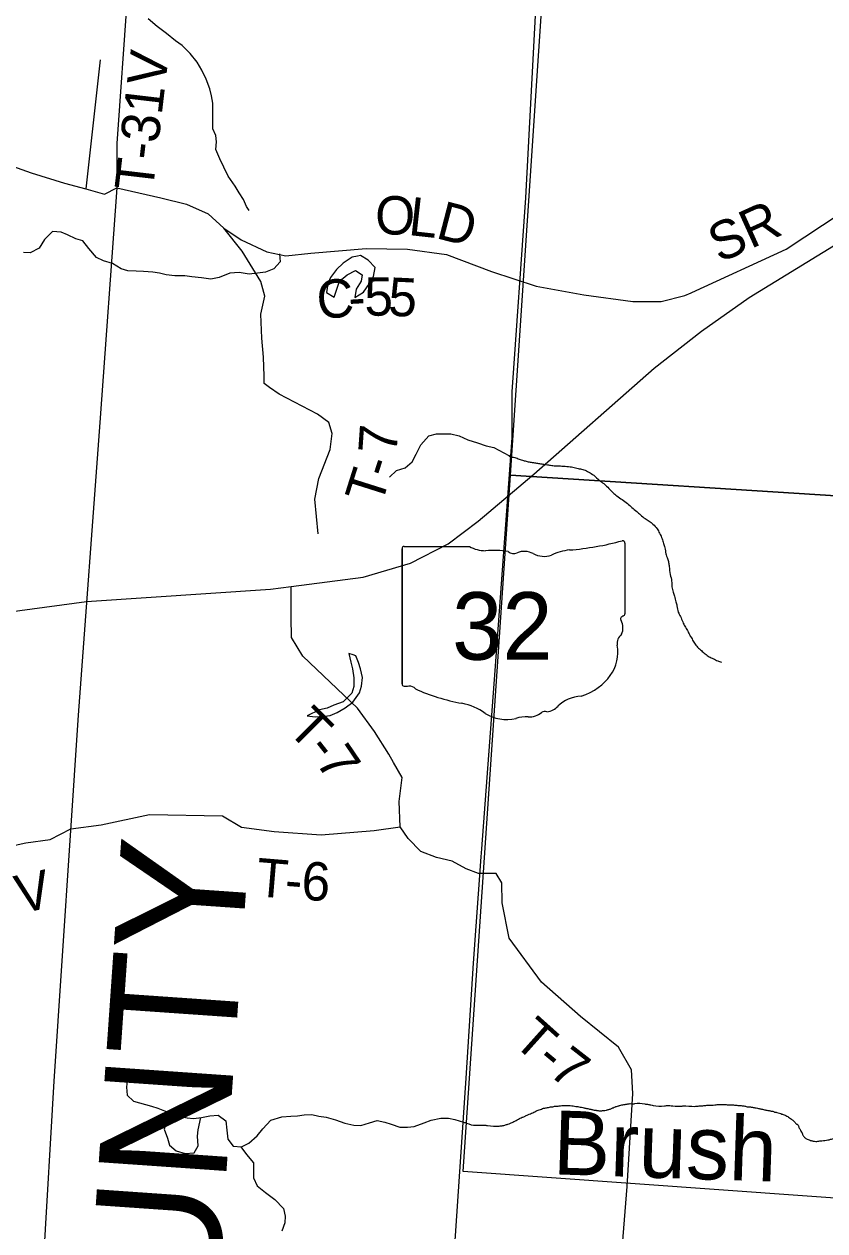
# Model space of a CAD drawing. Extents: x -15 to 405, y -40 to 87.
# Drawn here: x 3.536 to 4.721, y 17.808 to 19.593 of the extents above; entities that cross this region are included whole.
import ezdxf

# ---------------------------------------------------------------- set-up
doc = ezdxf.new("R2010")
doc.units = 0
for name, color, linetype in [('GM_P_State_Alignment', 7, 'Continuous'), ('GM_P_State_Location', 7, 'Continuous'), ('GM_X_Adjacent_County_Text', 7, 'Continuous'), ('GM_X_Airport_Location_Class_2', 7, 'Continuous'), ('GM_X_Minor_Lake', 7, 'Continuous'), ('GM_X_Minor_Lake_Text', 7, 'Continuous'), ('GM_X_Minor_River', 7, 'Continuous'), ('GM_X_Section_Text', 7, 'Continuous'), ('GM_X_State_Location', 7, 'Continuous'), ('GM_X_State_Route', 7, 'Continuous'), ('GM_X_Township_Subdivision', 7, 'Continuous'), ('GM_X_Township_Text', 7, 'Continuous')]:
    doc.layers.add(name, color=color, linetype=linetype)

msp = doc.modelspace()

# ---------------------------------------------------------------- linework, layer by layer
at = {"layer": 'GM_P_State_Location'}
for points in [[(3.6488, 19.5407), (3.6273, 19.3495)], [(3.9712, 18.839), (3.9663, 18.8906), (3.9723, 18.921), (3.989, 18.9639), (3.9916, 18.9878), (3.9871, 19.0038), (3.97, 19.0163), (3.9134, 19.0459), (3.8993, 19.0555), (3.8911, 19.0615), (3.8913, 19.0725), (3.8902, 19.1006), (3.8879, 19.1287), (3.8863, 19.1644), (3.892, 19.1906), (3.8863, 19.2126), (3.8586, 19.2574), (3.8316, 19.2916)], [(4.0826, 18.5005), (4.0824, 18.5008), (4.0755, 18.5128), (4.0546, 18.5466), (4.0291, 18.5811), (3.9482, 18.6582), (3.9318, 18.6859), (3.9314, 18.7159), (3.9312, 18.7613)], [(4.4151, 17.7062), (4.4283, 17.8734), (4.4366, 18.0109), (4.4347, 18.0458), (4.4156, 18.0792), (4.359, 18.1248), (4.3017, 18.1756), (4.2538, 18.2409), (4.2435, 18.293), (4.2427, 18.3226), (4.2343, 18.3363), (4.2188, 18.3363), (4.2081, 18.3362), (4.1899, 18.3435), (4.1694, 18.3545), (4.1462, 18.3601), (4.123, 18.3689), (4.104, 18.3882), (4.0926, 18.4053), (4.0911, 18.4429), (4.0953, 18.4786), (4.0826, 18.5005)], [(3.2241, 18.2382), (3.247, 18.2857), (3.2998, 18.3863), (3.3118, 18.4075), (3.3179, 18.4159), (3.3273, 18.4167), (3.3687, 18.4077), (3.3941, 18.4001), (3.4374, 18.3805), (3.4658, 18.3688), (3.4829, 18.367), (3.5071, 18.375), (3.5389, 18.3819), (3.5749, 18.3869), (3.605, 18.4026)], [(3.605, 18.4026), (3.6499, 18.4085), (3.7216, 18.4237), (3.8298, 18.4219), (3.8576, 18.4048), (3.9062, 18.3987), (3.9753, 18.3935), (4.0539, 18.4), (4.0926, 18.4053)]]:
    msp.add_lwpolyline(points, dxfattribs=at)
at = {"layer": 'GM_X_Adjacent_County_Text'}
for points in [[(3.8692, 19.3175), (3.8652, 19.3236), (3.8607, 19.3338), (3.8542, 19.3436), (3.8485, 19.3535), (3.8379, 19.3683), (3.8315, 19.3815), (3.8258, 19.394), (3.8197, 19.4077), (3.8208, 19.419), (3.8197, 19.4285), (3.8151, 19.4384), (3.8151, 19.4486), (3.8155, 19.4623), (3.8151, 19.4763), (3.8135, 19.4873), (3.8109, 19.4975), (3.8052, 19.5119), (3.7991, 19.5255), (3.7923, 19.5373), (3.782, 19.5498), (3.7699, 19.5619), (3.76, 19.5687), (3.7468, 19.5793), (3.7331, 19.5899), (3.7195, 19.6013)], [(3.9139, 19.2536), (3.915, 19.2417), (3.9055, 19.2311), (3.893, 19.2265), (3.8816, 19.2246), (3.8688, 19.2235), (3.8544, 19.2257), (3.8404, 19.225), (3.8248, 19.2185), (3.8123, 19.2158), (3.7987, 19.2181), (3.7843, 19.2192), (3.7737, 19.2207), (3.7593, 19.2207), (3.7464, 19.2222), (3.7366, 19.2248), (3.7267, 19.2263), (3.7127, 19.2274), (3.7021, 19.2278), (3.6896, 19.2282), (3.6797, 19.2312), (3.6669, 19.2391), (3.6536, 19.2433), (3.643, 19.2482), (3.632, 19.2614), (3.6229, 19.2728), (3.6126, 19.2758), (3.6005, 19.2815), (3.5907, 19.2857), (3.5782, 19.2864), (3.5664, 19.2746), (3.5585, 19.2617), (3.5452, 19.2549), (3.5354, 19.2556)], [(4.0768, 18.9228), (4.0869, 18.933), (4.0998, 18.9368), (4.11, 18.9455), (4.1161, 18.9569), (4.1232, 18.971), (4.135, 18.9839), (4.1463, 18.9873), (4.1672, 18.9873), (4.1797, 18.9843), (4.1925, 18.9783), (4.2066, 18.9737), (4.2195, 18.9692), (4.2312, 18.9669), (4.2533, 18.9549)], [(3.6885, 18.0298), (3.6876, 18.0201), (3.6884, 18.0084), (3.6979, 17.9997), (3.7244, 17.9921), (3.7339, 17.9891), (3.7437, 17.9853), (3.7566, 17.9804), (3.7661, 17.9774), (3.7771, 17.9748), (3.7866, 17.974), (3.7983, 17.9755), (3.8108, 17.9778), (3.8233, 17.9786), (3.8347, 17.9703), (3.8362, 17.9566), (3.8374, 17.943), (3.8453, 17.9331), (3.8578, 17.932), (3.8684, 17.9373), (3.8809, 17.948), (3.8892, 17.9586), (3.901, 17.9715), (3.9172, 17.9761), (3.9305, 17.9772), (3.9403, 17.9776), (3.9506, 17.9792), (3.9619, 17.9799), (3.9722, 17.9773), (3.9828, 17.9758), (3.9968, 17.9716), (4.0104, 17.9671), (4.0237, 17.9637), (4.0343, 17.9634), (4.0468, 17.9675), (4.0585, 17.971), (4.0695, 17.9683), (4.079, 17.9653), (4.0919, 17.9612), (4.1032, 17.9608), (4.1131, 17.962), (4.1279, 17.9673), (4.1385, 17.9711), (4.1525, 17.9741), (4.1638, 17.9742), (4.1733, 17.9723), (4.1862, 17.9685)], [(3.7517, 17.9823), (3.7472, 17.9705), (3.7434, 17.958), (3.748, 17.9448), (3.751, 17.9345), (3.7612, 17.9258), (3.7745, 17.922), (3.7878, 17.9228), (3.7934, 17.9334), (3.7927, 17.9475), (3.7938, 17.957), (3.7977, 17.9755)], [(3.8565, 17.9321), (3.865, 17.9203), (3.8753, 17.9082), (3.8753, 17.8862), (3.881, 17.874), (3.8931, 17.8642), (3.9068, 17.854), (3.9197, 17.8407), (3.9223, 17.8293), (3.9216, 17.8195), (3.9175, 17.807)]]:
    msp.add_lwpolyline(points, dxfattribs=at)
for points in [[(4.2533, 18.9557), (4.2533, 18.9549), (4.26, 18.9524), (4.2668, 18.9503), (4.2732, 18.9482), (4.2788, 18.9465), (4.2845, 18.9452), (4.2913, 18.9442), (4.2969, 18.9432), (4.3034, 18.9423), (4.3102, 18.9413), (4.3166, 18.9403), (4.3238, 18.9397), (4.3314, 18.9394), (4.3416, 18.9387), (4.3499, 18.9373), (4.3574, 18.9355), (4.3642, 18.9338), (4.3713, 18.9305), (4.3787, 18.9257), (4.3872, 18.9182), (4.3935, 18.9134), (4.4012, 18.906), (4.4071, 18.9001), (4.413, 18.8953), (4.4208, 18.8897), (4.4286, 18.8838), (4.4352, 18.8782), (4.4423, 18.8723), (4.4478, 18.8672), (4.4548, 18.8616), (4.4608, 18.858), (4.4663, 18.8533), (4.4725, 18.8466), (4.4761, 18.84), (4.48, 18.8316), (4.4817, 18.825), (4.4841, 18.8185), (4.4854, 18.8097), (4.4878, 18.8024), (4.4895, 18.7967), (4.4904, 18.7906), (4.4919, 18.7791), (4.4939, 18.7692), (4.4943, 18.7604), (4.4964, 18.7528), (4.4981, 18.747), (4.5001, 18.7382), (4.5018, 18.7324), (4.5037, 18.7233), (4.5069, 18.7167), (4.5105, 18.7086), (4.5133, 18.7024), (4.5173, 18.6958), (4.5208, 18.6893), (4.5241, 18.6835), (4.5277, 18.6773), (4.5324, 18.6714), (4.5379, 18.6663), (4.5435, 18.6615), (4.5494, 18.6572), (4.5557, 18.6543), (4.5621, 18.651), (4.5677, 18.649)], [(4.1862, 17.9685), (4.1905, 17.967), (4.2041, 17.9638), (4.2068, 17.9641), (4.2129, 17.9639), (4.2189, 17.9637), (4.2216, 17.9633), (4.239, 17.9627), (4.2421, 17.963), (4.2444, 17.9633), (4.247, 17.9639), (4.2497, 17.965), (4.2516, 17.9653), (4.2555, 17.9667), (4.2605, 17.9692), (4.2674, 17.9728), (4.2728, 17.9756), (4.2751, 17.9763), (4.279, 17.9781), (4.2833, 17.9802), (4.2902, 17.983), (4.2964, 17.9862), (4.2998, 17.9873), (4.3063, 17.9893), (4.309, 17.9896), (4.3147, 17.9909), (4.3182, 17.9912), (4.3208, 17.9919), (4.3277, 17.9924), (4.3315, 17.993), (4.3342, 17.993), (4.3391, 17.9932), (4.3418, 17.9931), (4.3463, 17.9926), (4.3482, 17.9925), (4.3523, 17.9916), (4.355, 17.9915), (4.3588, 17.9906), (4.3607, 17.9906), (4.364, 17.9897), (4.3655, 17.9893), (4.3682, 17.9888), (4.3716, 17.9879), (4.3731, 17.9875), (4.3746, 17.9874), (4.3765, 17.987), (4.378, 17.9866), (4.3806, 17.9861), (4.3821, 17.9861), (4.3836, 17.9856), (4.3855, 17.9856), (4.3874, 17.9851), (4.3897, 17.985), (4.3916, 17.9854), (4.3935, 17.9857), (4.3969, 17.9859), (4.3985, 17.9867), (4.4, 17.987), (4.4019, 17.9877), (4.4038, 17.988), (4.4058, 17.9891), (4.4073, 17.9898), (4.4108, 17.9912), (4.4123, 17.9915), (4.4154, 17.9925), (4.4169, 17.9929), (4.4204, 17.9939), (4.4219, 17.9942), (4.4246, 17.9945), (4.4261, 17.9949), (4.4284, 17.9952), (4.4299, 17.9955), (4.4326, 17.9958), (4.4375, 17.9956), (4.4394, 17.9959), (4.4542, 17.9954), (4.4565, 17.995), (4.4584, 17.9949), (4.4606, 17.9945), (4.4633, 17.994), (4.4666, 17.9931), (4.4833, 17.9926), (4.4864, 17.9929), (4.4959, 17.9925), (4.5084, 17.9921), (4.5107, 17.9924), (4.5285, 17.9918), (4.5315, 17.9921), (4.5349, 17.9924), (4.5388, 17.9926), (4.5445, 17.9932), (4.5471, 17.9935), (4.5532, 17.9937), (4.5578, 17.9939)], [(4.5578, 17.9939), (4.5597, 17.9942), (4.5654, 17.9944), (4.5673, 17.9944), (4.5734, 17.9945), (4.576, 17.9941), (4.5855, 17.9938), (4.5919, 17.9932), (4.5938, 17.9931), (4.5999, 17.9925), (4.6021, 17.9921), (4.6044, 17.9916), (4.607, 17.9911), (4.6093, 17.9911), (4.6116, 17.9906), (4.6138, 17.9905), (4.6153, 17.9901), (4.6172, 17.9897), (4.6191, 17.9896), (4.6225, 17.9887), (4.6244, 17.9883), (4.627, 17.9878), (4.63, 17.987), (4.6346, 17.986), (4.638, 17.9856), (4.6402, 17.9851), (4.6421, 17.9847), (4.6448, 17.9842), (4.6463, 17.9834), (4.6478, 17.9833), (4.6496, 17.9825), (4.6534, 17.9816), (4.6572, 17.9804), (4.659, 17.9799), (4.6617, 17.9787), (4.6669, 17.9759), (4.6724, 17.9719), (4.6758, 17.9687), (4.6787, 17.9656), (4.6802, 17.9648), (4.6816, 17.9625), (4.6823, 17.9605), (4.6845, 17.9567), (4.6852, 17.9551), (4.687, 17.9524), (4.6873, 17.9509), (4.688, 17.9493), (4.6891, 17.9478), (4.6924, 17.9442), (4.6946, 17.943), (4.6973, 17.9422), (4.6991, 17.9414), (4.7014, 17.9409), (4.7033, 17.9405), (4.7074, 17.9399), (4.7101, 17.9402), (4.7162, 17.9408), (4.725, 17.942), (4.7292, 17.943), (4.7349, 17.9447), (4.7368, 17.945), (4.7387, 17.9435), (4.7401, 17.9411), (4.7415, 17.9381), (4.743, 17.9353), (4.7441, 17.9334), (4.7451, 17.9319), (4.7469, 17.928), (4.748, 17.9264), (4.7505, 17.9226), (4.7509, 17.921), (4.753, 17.9172), (4.7548, 17.9144), (4.7559, 17.9129), (4.757, 17.9109), (4.758, 17.9086), (4.7598, 17.9052), (4.762, 17.9009), (4.7641, 17.8978), (4.7659, 17.8939), (4.7669, 17.8912), (4.7691, 17.8881), (4.7706, 17.8854), (4.7723, 17.8819), (4.7734, 17.8792), (4.7748, 17.8765), (4.7766, 17.8727), (4.7776, 17.87), (4.7791, 17.8673), (4.7812, 17.8619), (4.7833, 17.858), (4.7843, 17.8542), (4.7865, 17.8515), (4.7887, 17.848), (4.7904, 17.8437), (4.7926, 17.841), (4.7937, 17.8391)]]:
    msp.add_spline(points, degree=3, dxfattribs=at)
at = {"layer": 'GM_X_Airport_Location_Class_2'}
for points in [[(5.3465, 19.8721), (5.28, 18.8608), (4.2557, 18.9261), (4.3229, 19.9309)], [(4.2557, 18.9261), (5.28, 18.8608), (5.2536, 18.4962), (5.2191, 18.0246), (5.2034, 17.8226), (4.1856, 17.8953)]]:
    msp.add_lwpolyline(points, close=True, dxfattribs=at)
msp.add_lwpolyline([(4.047, 15.9545), (4.0777, 16.4138), (4.1093, 16.7849), (4.1132, 16.8456), (4.1173, 16.8769), (4.1204, 16.9125), (4.1207, 16.9338), (4.126, 17.0077), (4.1648, 17.662), (4.1898, 18.0333), (4.2008, 18.2037), (4.2124, 18.3609), (4.2133, 18.373), (4.2327, 18.6367), (4.2582, 18.9809), (4.2581, 19.0493), (4.2782, 19.3362), (4.2938, 19.625)], dxfattribs=at)
at = {"layer": 'GM_X_Section_Text'}
for points in [[(4.0291, 19.25), (4.0214, 19.2483), (4.0081, 19.2396), (3.9983, 19.2305), (3.9892, 19.2183), (3.9855, 19.2089), (3.9832, 19.1963), (3.9946, 19.1895)], [(3.9946, 19.1895), (3.9991, 19.2024), (4.0029, 19.2131), (4.0142, 19.2222), (4.0263, 19.2286), (4.0362, 19.2226), (4.0347, 19.2131), (4.0275, 19.2013), (4.0253, 19.1888), (4.0381, 19.1968), (4.0468, 19.2097), (4.0529, 19.2199), (4.0555, 19.2332), (4.0453, 19.2442), (4.0335, 19.251), (4.0291, 19.25)], [(4.0227, 18.6598), (4.0164, 18.6618), (4.0195, 18.6493), (4.0217, 18.6394), (4.024, 18.6258), (4.024, 18.6129), (4.021, 18.6034), (4.0082, 18.5905), (3.9945, 18.5855), (3.9843, 18.581), (3.973, 18.5787), (3.9548, 18.5696)], [(3.9548, 18.5696), (3.9669, 18.5681), (3.9775, 18.5688), (3.9889, 18.5704), (3.9991, 18.5746), (4.0112, 18.5818), (4.0226, 18.5901), (4.032, 18.6038), (4.0354, 18.6137), (4.0369, 18.6266), (4.0335, 18.6391), (4.0308, 18.6489), (4.027, 18.6584), (4.0227, 18.6598)]]:
    msp.add_lwpolyline(points, dxfattribs=at)
at = {"layer": 'GM_X_State_Location'}
for points in [[(3.6285, 18.7389), (3.9004, 18.7574), (3.9312, 18.7613), (4.0377, 18.7747), (4.1078, 18.7957), (4.1635, 18.8242), (4.2079, 18.8577), (4.2901, 18.9273), (4.4681, 19.0844), (4.5379, 19.1388), (4.6087, 19.1886), (4.8734, 19.3513)], [(2.1045, 18.5677), (2.1196, 18.5764), (2.2112, 18.6006), (2.2798, 18.6044), (2.4597, 18.6209), (2.7276, 18.6453), (2.8994, 18.661), (3.3688, 18.7037), (3.6285, 18.7389)]]:
    msp.add_lwpolyline(points, dxfattribs=at)
at = {"layer": 'GM_X_State_Route'}
for p, q in [((3.6935, 19.7035), (3.6734, 19.4166)), ((3.6734, 19.4166), (3.6733, 19.351)), ((3.6733, 19.351), (3.648, 19.004)), ((3.648, 19.004), (3.6161, 18.5709)), ((3.6161, 18.5709), (3.5801, 18.0292)), ((3.5801, 18.0292), (3.5413, 17.375))]:
    msp.add_line(p, q, dxfattribs=at)
at = {"layer": 'GM_X_Township_Subdivision'}
for p, q in [((4.4249, 18.8254), (4.4249, 18.7208)), ((4.0953, 18.817), (4.0953, 18.6169)), ((4.0953, 18.6169), (4.0953, 18.817)), ((4.0953, 18.6169), (4.0953, 18.817)), ((4.0985, 18.8205), (4.1951, 18.8205)), ((4.4248, 18.7208), (4.4249, 18.7208))]:
    msp.add_line(p, q, dxfattribs=at)
for centre, major_axis, start_param, end_param in [((4.3075, 19.0933), (0.3495, 0), 4.814394, 5.042369), ((4.4212, 18.8259), (0.00367, 0), 6.141152, 7.989035), ((4.0991, 18.8175), (0.00382, 0), 1.712693, 3.28349), ((4.218, 18.8437), (0.037, 0), 4.042523, 4.731795), ((4.2303, 18.7081), (0.133, 0), 1.404758, 1.657858), ((4.2605, 18.8185), (0.0107, 0), 3.836095, 5.185415), ((4.2762, 18.7954), (0.0222, 0), 0.950623, 2.079405), ((4.3049, 18.8271), (0.0267, 0), 4.081561, 5.145723), ((4.3521, 18.7594), (0.0703, 0), 1.699011, 2.107814), ((4.424, 18.7131), (0.00568, 0), 1.883978, 3.671073), ((4.421, 18.7204), (0.00393, 0), 5.05454, 6.418171), ((4.3879, 18.6998), (0.0341, 0), 5.934695, 6.695948), ((4.438, 18.6769), (0.0248, 0), 2.387724, 3.262537), ((4.3271, 18.6636), (0.0874, 0), 5.101752, 6.440018), ((4.0991, 18.6165), (0.00385, 0), 3.00124, 4.508301), ((4.0997, 18.637), (0.0294, 0), 4.665946, 4.897461), ((4.1057, 18.6054), (0.0106, 0), 0.519207, 1.627899), ((4.2395, 18.7852), (0.2524, 0), 4.195997, 4.488961), ((4.3639, 18.5607), (0.0479, 0), 1.647645, 2.488434), ((4.1643, 18.527), (0.079, 0), 0.823519, 1.323587), ((4.2497, 18.6044), (0.0501, 0), 4.026481, 4.996735), ((4.2823, 18.5894), (0.0267, 0), 4.691044, 5.507374), ((4.3065, 18.57), (0.00752, 0), 1.147584, 2.315152), ((4.3033, 18.5975), (0.0282, 0), 4.937069, 5.64225), ((4.2786, 18.5352), (0.0412, 0), 1.495662, 1.94098)]:
    msp.add_ellipse(centre, major_axis=major_axis, ratio=0.8, start_param=start_param, end_param=end_param, dxfattribs=at)
at = {"layer": 'GM_X_Township_Text'}
for points in [[(4.5228, 19.1959), (4.5237, 19.1963), (4.6636, 19.2602), (4.852, 19.3852), (4.9689, 19.4659)], [(3.3301, 19.3921), (3.3445, 19.405), (3.3638, 19.4172), (3.3702, 19.4194), (3.3764, 19.4206), (3.3918, 19.4213), (3.402, 19.4204), (3.4118, 19.4182), (3.4275, 19.4139), (3.465, 19.4038), (3.4965, 19.391), (3.5466, 19.3733), (3.5959, 19.3582), (3.6273, 19.3495), (3.6551, 19.3417), (3.6733, 19.351)], [(3.6733, 19.351), (3.7383, 19.3361), (3.7762, 19.3269), (3.8084, 19.3125), (3.8316, 19.2916), (3.8574, 19.2741), (3.895, 19.2563), (3.9235, 19.2506), (3.9603, 19.2544), (4.042, 19.2613), (4.1031, 19.2606), (4.1608, 19.2526), (4.2277, 19.2272), (4.2934, 19.2056), (4.3641, 19.1928), (4.4366, 19.1829), (4.4784, 19.183), (4.5137, 19.1917), (4.5228, 19.1959)]]:
    msp.add_lwpolyline(points, dxfattribs=at)

# ---------------------------------------------------------------- texts
at = {"layer": 'GM_P_State_Alignment'}
msp.add_text('MEIGS  COUNTY', height=0.189394, rotation=86.0177, dxfattribs=at).set_placement((3.7285, 16.3593))
at = {"layer": 'GM_X_Minor_Lake'}
for s, height, rotation, p in [('O', 0.0568, 358.2366, (4.0546, 19.2829)), ('L', 0.0568, 353.666, (4.1033, 19.2815)), ('D', 0.0568, 345.4253, (4.1435, 19.2772)), ('SR', 0.05682, 24.3048, (4.5647, 19.2394)), ('C', 0.0568, 4.1603, (3.9709, 19.157)), ('5', 0.0568, 0.6922, (4.0398, 19.1617)), ('5', 0.0568, 357.194, (4.0739, 19.1621)), ('-', 0.0568, 3.2959, (4.0172, 19.1604))]:
    msp.add_text(s, height=height, rotation=rotation, dxfattribs=at).set_placement(p)
at = {"layer": 'GM_X_Minor_Lake_Text'}
msp.add_text('Brush', height=0.09469, rotation=358.1026, dxfattribs=at).set_placement((4.3175, 17.8913))
at = {"layer": 'GM_X_Minor_River'}
for s, height, rotation, p in [('T-31V', 0.05682, 83.2899, (3.7263, 19.3448)), ('7', 0.0568, 85.9944, (4.0869, 18.9563)), ('-', 0.0568, 72.1575, (4.077, 18.9197)), ('T', 0.0568, 72.4182, (4.0642, 18.8792)), ('T', 0.0568, 314.8197, (3.9235, 18.5483)), ('-', 0.0568, 308.1502, (3.9523, 18.5194)), ('7', 0.0568, 304.1346, (3.9661, 18.502)), ('T', 0.0568, 355.2203, (3.8778, 18.303)), ('V', 0.0568, 12.3806, (3.5303, 18.2765)), ('6', 0.0568, 357.0769, (3.9454, 18.2975)), ('-', 0.0568, 355.4995, (3.9205, 18.2995)), ('T', 0.0568, 318.1668, (4.2571, 18.0856)), ('7', 0.0568, 322.061, (4.3099, 18.0397)), ('-', 0.0568, 320.2697, (4.2905, 18.0558))]:
    msp.add_text(s, height=height, rotation=rotation, dxfattribs=at).set_placement(p)
at = {"layer": 'GM_X_Township_Subdivision'}
msp.add_text('32', height=0.1, dxfattribs=at).set_placement((4.1692, 18.6527))

doc.saveas('drawing.dxf')
